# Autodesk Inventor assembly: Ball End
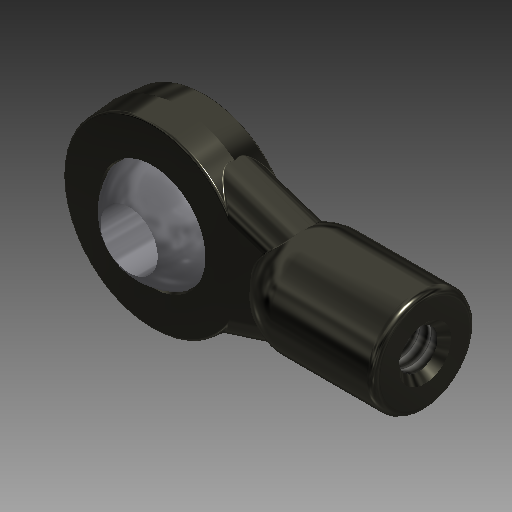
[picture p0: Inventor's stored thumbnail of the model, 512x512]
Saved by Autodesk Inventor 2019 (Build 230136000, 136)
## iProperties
Shininess: 50.0
Compacted: True
Length Units: 11272
Angle Units: 11279
Time Units: 11290
Mass Units: 11286
Length Display Precision: 4
Angle Display Precision: 2
Company: Autodesk
Manager: Lebovitz
Created: 2000-03
Part Number: Ball End
Project: Inventor Samples
User Status: IN PROGRESS
Document SubType Name: Assembly
Designer: The PD Team
Mass: 0.70348 g
Surface Area: 6.19952 cm^2
Volume: 0.425844 cm^3
Density: 1.65196 g/cm^3
Density: 0.0
Volumn: 0.0
Area: 0.0
PropertySet Name: Model Information
Control State: 0
Master: False
Checked Out: False
Checked Out Date: 2018-05-30
Last Check In Date: 2018-05-30
Author: The PD Team
Revision Number: A
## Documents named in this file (3)
- C:\Users\itools\Desktop\autodesk_inventor_2018_samples\Models\Assemblies\Suspension\Components\Ball End.iam
- C:\Users\itools\Desktop\autodesk_inventor_2018_samples\Models\Assemblies\Suspension\Components\Ball End.ipt
- C:\Users\itools\Desktop\autodesk_inventor_2018_samples\Models\Assemblies\Suspension\Components\0.25 Ball.ipt
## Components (2 placed, 2 different names)
1. Ball End:1 — Mate:1, Angle:1
2. 0.25 Ball:1 — Mate:1, Angle:1
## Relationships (2: Mate 1, Angle 1)
- Mate:1: Ball End:1 ↔ 0.25 Ball:1
- Angle:1: Ball End:1 ↔ 0.25 Ball:1
